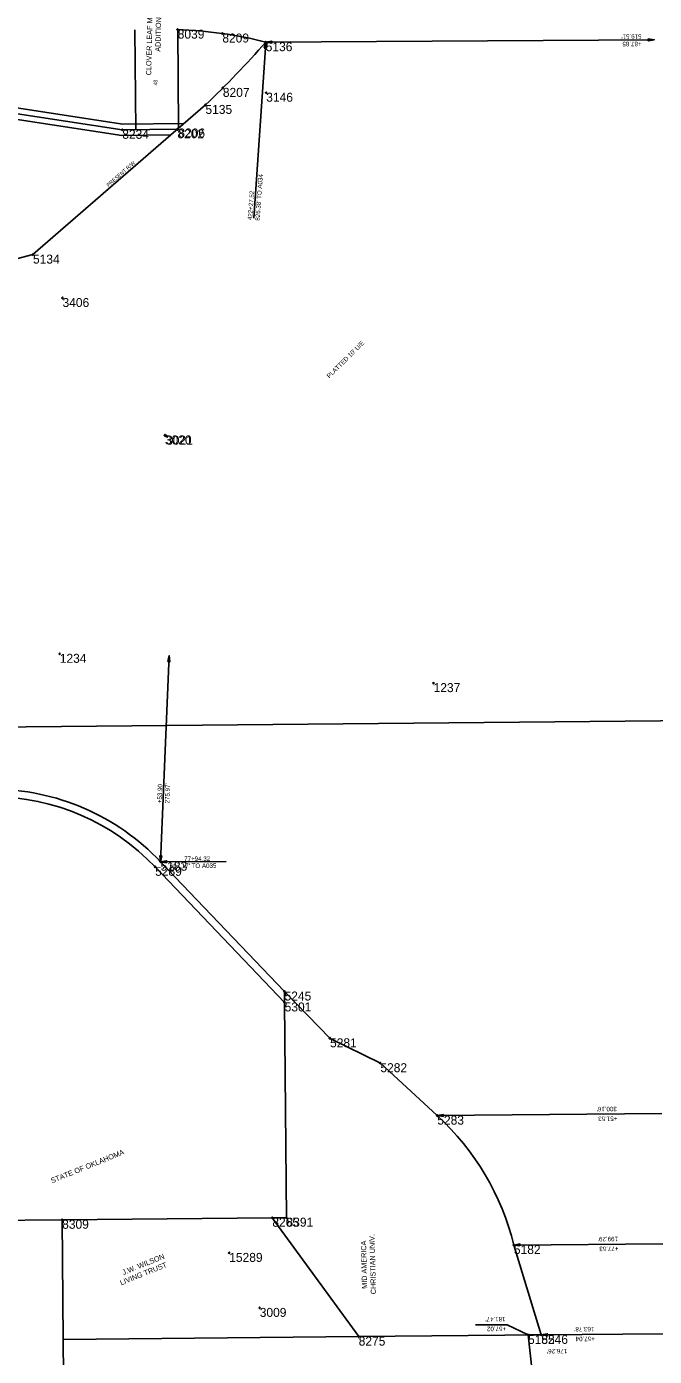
# Model space of a CAD drawing. Extents: x 2145146 to 2158053, y 137507 to 150829.
# Drawn here: x 2149980 to 2150819, y 142146 to 143925 of the extents above; entities that cross this region are included whole.
import ezdxf

# ---------------------------------------------------------------- set-up
doc = ezdxf.new("R2010")
doc.units = 0
for name, color, linetype in [('ALIGN_Cogo Points', 7, 'Continuous'), ('ALIGN_ROW Dimension', 7, 'Continuous'), ('ALIGN_ROW Line', 7, 'Continuous'), ('ALIGN_ROW Text', 7, 'Continuous'), ('PLSS_Easement', 7, 'Continuous'), ('PLSS_Lot Line', 7, 'Continuous'), ('PLSS_Property Line', 7, 'Continuous'), ('PLSS_Section Line', 7, 'Continuous'), ('PLSS_Text', 7, 'Continuous'), ('PLSS_Text_TURNED OFF', 7, 'Continuous')]:
    doc.layers.add(name, color=color, linetype=linetype)

# ---------------------------------------------------------------- blocks, each defined once
blk = doc.blocks.new('Arrowhd')
at = {"layer": 'PLSS_Property Line'}
blk.add_lwpolyline([(0.125, -0.021), (0.125, 0.021), (0, 0)], close=True, dxfattribs=at)

msp = doc.modelspace()

# ---------------------------------------------------------------- linework, layer by layer
at = {"layer": 'ALIGN_Cogo Points'}
for points in [[(2150182, 143920.7), (2150182, 143921.9), (2150182, 143920.7), (2150180.8, 143920.7), (2150182, 143920.7), (2150182, 143919.5), (2150182, 143920.7), (2150183.2, 143920.7)], [(2150241.7, 143915.5), (2150241.7, 143916.7), (2150241.7, 143915.5), (2150240.5, 143915.5), (2150241.7, 143915.5), (2150241.7, 143914.3), (2150241.7, 143915.5), (2150242.9, 143915.5)], [(2150299.7, 143903.9), (2150299.7, 143905.1), (2150299.7, 143903.9), (2150298.5, 143903.9), (2150299.7, 143903.9), (2150299.7, 143902.7), (2150299.7, 143903.9), (2150300.9, 143903.9)], [(2150242.4, 143842.8), (2150242.4, 143844), (2150242.4, 143842.8), (2150241.2, 143842.8), (2150242.4, 143842.8), (2150242.4, 143841.6), (2150242.4, 143842.8), (2150243.6, 143842.8)], [(2150300.4, 143836.3), (2150300.4, 143837.5), (2150300.4, 143836.3), (2150299.2, 143836.3), (2150300.4, 143836.3), (2150300.4, 143835.1), (2150300.4, 143836.3), (2150301.6, 143836.3)], [(2150219.1, 143820), (2150219.1, 143821.2), (2150219.1, 143820), (2150217.9, 143820), (2150219.1, 143820), (2150219.1, 143818.8), (2150219.1, 143820), (2150220.3, 143820)], [(2150107.9, 143786.7), (2150107.9, 143787.9), (2150107.9, 143786.7), (2150106.7, 143786.7), (2150107.9, 143786.7), (2150107.9, 143785.5), (2150107.9, 143786.7), (2150109.1, 143786.7)], [(2150181.6, 143787.4), (2150181.6, 143788.6), (2150181.6, 143787.4), (2150180.4, 143787.4), (2150181.6, 143787.4), (2150181.6, 143786.2), (2150181.6, 143787.4), (2150182.8, 143787.4)], [(2150182.9, 143788.5), (2150182.9, 143789.7), (2150182.9, 143788.5), (2150181.7, 143788.5), (2150182.9, 143788.5), (2150182.9, 143787.3), (2150182.9, 143788.5), (2150184.1, 143788.5)], [(2149988.5, 143619.8), (2149988.5, 143621), (2149988.5, 143619.8), (2149987.3, 143619.8), (2149988.5, 143619.8), (2149988.5, 143618.6), (2149988.5, 143619.8), (2149989.7, 143619.8)], [(2150028, 143561.7), (2150028, 143562.9), (2150028, 143561.7), (2150026.8, 143561.7), (2150028, 143561.7), (2150028, 143560.5), (2150028, 143561.7), (2150029.2, 143561.7)], [(2150164.9, 143378), (2150164.9, 143379.2), (2150164.9, 143378), (2150163.7, 143378), (2150164.9, 143378), (2150164.9, 143376.8), (2150164.9, 143378), (2150166.1, 143378)], [(2150166.5, 143377.5), (2150166.5, 143378.7), (2150166.5, 143377.5), (2150165.3, 143377.5), (2150166.5, 143377.5), (2150166.5, 143376.3), (2150166.5, 143377.5), (2150167.7, 143377.5)], [(2150024.3, 143085.8), (2150024.3, 143087), (2150024.3, 143085.8), (2150023.1, 143085.8), (2150024.3, 143085.8), (2150024.3, 143084.6), (2150024.3, 143085.8), (2150025.5, 143085.8)], [(2150524.2, 143046.6), (2150524.2, 143047.8), (2150524.2, 143046.6), (2150523, 143046.6), (2150524.2, 143046.6), (2150524.2, 143045.4), (2150524.2, 143046.6), (2150525.4, 143046.6)], [(2150151.8, 142800.9), (2150151.8, 142802.1), (2150151.8, 142800.9), (2150150.6, 142800.9), (2150151.8, 142800.9), (2150151.8, 142799.7), (2150151.8, 142800.9), (2150153, 142800.9)], [(2150159.1, 142807.7), (2150159.1, 142808.9), (2150159.1, 142807.7), (2150157.9, 142807.7), (2150159.1, 142807.7), (2150159.1, 142806.5), (2150159.1, 142807.7), (2150160.3, 142807.7)], [(2150324.9, 142634.1), (2150324.9, 142635.3), (2150324.9, 142634.1), (2150323.7, 142634.1), (2150324.9, 142634.1), (2150324.9, 142632.9), (2150324.9, 142634.1), (2150326.1, 142634.1)], [(2150325, 142619.5), (2150325, 142620.7), (2150325, 142619.5), (2150323.8, 142619.5), (2150325, 142619.5), (2150325, 142618.3), (2150325, 142619.5), (2150326.2, 142619.5)], [(2150385.7, 142571.5), (2150385.7, 142572.7), (2150385.7, 142571.5), (2150384.5, 142571.5), (2150385.7, 142571.5), (2150385.7, 142570.3), (2150385.7, 142571.5), (2150386.9, 142571.5)], [(2150453, 142538.2), (2150453, 142539.4), (2150453, 142538.2), (2150451.8, 142538.2), (2150453, 142538.2), (2150453, 142537), (2150453, 142538.2), (2150454.2, 142538.2)], [(2150529.1, 142468.1), (2150529.1, 142469.3), (2150529.1, 142468.1), (2150527.9, 142468.1), (2150529.1, 142468.1), (2150529.1, 142466.9), (2150529.1, 142468.1), (2150530.3, 142468.1)], [(2150027.5, 142328.8), (2150027.5, 142330), (2150027.5, 142328.8), (2150026.3, 142328.8), (2150027.5, 142328.8), (2150027.5, 142327.6), (2150027.5, 142328.8), (2150028.7, 142328.8)], [(2150308.5, 142331.5), (2150308.5, 142332.7), (2150308.5, 142331.5), (2150307.3, 142331.5), (2150308.5, 142331.5), (2150308.5, 142330.3), (2150308.5, 142331.5), (2150309.7, 142331.5)], [(2150327.5, 142331.6), (2150327.5, 142332.8), (2150327.5, 142331.6), (2150326.3, 142331.6), (2150327.5, 142331.6), (2150327.5, 142330.4), (2150327.5, 142331.6), (2150328.7, 142331.6)], [(2150250.9, 142284.5), (2150250.9, 142285.7), (2150250.9, 142284.5), (2150249.7, 142284.5), (2150250.9, 142284.5), (2150250.9, 142283.3), (2150250.9, 142284.5), (2150252.1, 142284.5)], [(2150631.5, 142295), (2150631.5, 142296.2), (2150631.5, 142295), (2150630.3, 142295), (2150631.5, 142295), (2150631.5, 142293.8), (2150631.5, 142295), (2150632.7, 142295)], [(2150291.7, 142210.9), (2150291.7, 142212.1), (2150291.7, 142210.9), (2150290.5, 142210.9), (2150291.7, 142210.9), (2150291.7, 142209.7), (2150291.7, 142210.9), (2150292.9, 142210.9)], [(2150650.4, 142174.7), (2150650.4, 142175.9), (2150650.4, 142174.7), (2150649.2, 142174.7), (2150650.4, 142174.7), (2150650.4, 142173.5), (2150650.4, 142174.7), (2150651.6, 142174.7)], [(2150668.1, 142174.8), (2150668.1, 142176), (2150668.1, 142174.8), (2150666.9, 142174.8), (2150668.1, 142174.8), (2150668.1, 142173.6), (2150668.1, 142174.8), (2150669.3, 142174.8)], [(2150424, 142172.5), (2150424, 142173.7), (2150424, 142172.5), (2150422.8, 142172.5), (2150424, 142172.5), (2150424, 142171.3), (2150424, 142172.5), (2150425.2, 142172.5)]]:
    msp.add_lwpolyline(points, dxfattribs=at)
at = {"layer": 'ALIGN_ROW Dimension'}
for points in [[(2150299.7, 143902.7), (2150283.9, 143668.5)], [(2150299.6, 143904), (2150819.2, 143907.1)], [(2150159.1, 142807.7), (2150170.6, 143083.4)], [(2150159.2, 142807.7), (2150247, 142807.9)], [(2150529.1, 142468.1), (2150829.3, 142470.8)], [(2150631.5, 142295), (2150830.8, 142296.8)], [(2150650.4, 142174.8), (2150622.4, 142188.4), (2150580.3, 142188.4)], [(2150668.1, 142174.8), (2150831.9, 142176.3)]]:
    msp.add_lwpolyline(points, dxfattribs=at)
for points in [[(2150168.9, 143075.4), (2150171.6, 143075.3), (2150170.6, 143083.4)], [(2150160.9, 142815.7), (2150158.2, 142815.8), (2150159.2, 142807.7)]]:
    msp.add_lwpolyline(points, close=True, dxfattribs=at)
at = {"layer": 'ALIGN_ROW Line'}
for points in [[(2149868, 143567.6), (2149863.4, 143587.1), (2149988.5, 143619.8), (2150172.9, 143779.8), (2150219.1, 143820)], [(2150159.1, 142807.7), (2150159.1, 142807.7), (2150324.9, 142634.1), (2150385.7, 142571.5), (2150453, 142538.2), (2150529.1, 142468.1)], [(2150631.5, 142295), (2150631.5, 142295), (2150668.1, 142174.8), (2150650.4, 142174.7), (2150656, 142126), (2150672.7, 142127.9), (2150688.4, 141967.3)]]:
    msp.add_lwpolyline(points, dxfattribs=at)
for centre, radius, start, end in [((2150164.9, 143378), 543, 75.6265, 88.2022), ((2149252.3, 144828.9), 1397.4, 313.7809, 318.5535), ((2149933.8, 142594.6), 310.1, 43.3958, 89.9357), ((2150291.7, 142210.9), 350.1, 13.9103, 47.2955)]:
    msp.add_arc(centre, radius, start, end, dxfattribs=at)
at = {"layer": 'PLSS_Easement'}
for points in [[(2149823.8, 143837.8), (2150108.5, 143794.2), (2150190.3, 143795)], [(2149827.6, 143822), (2150107.4, 143779.2), (2150172.9, 143779.8)], [(2150151.8, 142800.9), (2150151.8, 142800.9), (2150325, 142619.5), (2150324.9, 142634.1)]]:
    msp.add_lwpolyline(points, dxfattribs=at)
msp.add_arc((2149933.8, 142594.6), 300.1, 43.4233, 89.9173, dxfattribs=at)
at = {"layer": 'PLSS_Lot Line'}
for points in [[(2150125.9, 143786.9), (2150124.7, 143920.6)], [(2150182.9, 143788.5), (2150182, 143920.7)], [(2149804.3, 143833.2), (2150107.9, 143786.7), (2150181.6, 143787.4)]]:
    msp.add_lwpolyline(points, dxfattribs=at)
at = {"layer": 'PLSS_Property Line'}
for points in [[(2150424, 142172.5), (2150029, 142168.8), (2150027.5, 142328.8), (2149927.6, 142327.8), (2149922.4, 142907.1)], [(2150308.5, 142331.5), (2150327.5, 142331.6), (2150325, 142619.5)], [(2150308.5, 142331.5), (2150027.5, 142328.8)], [(2150308.5, 142331.5), (2150424, 142172.5), (2150668.1, 142174.8)], [(2150033.3, 141678.8), (2150029, 142168.8)]]:
    msp.add_lwpolyline(points, dxfattribs=at)
at = {"layer": 'PLSS_Section Line'}
msp.add_lwpolyline([(2148283.1, 142972.3), (2150921.7, 142997.3)], dxfattribs=at)

# ---------------------------------------------------------------- block references
at = {"layer": 'ALIGN_ROW Dimension'}
for p, xscale, yscale, rotation in [((2150299.7, 143904), 64.99999999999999, 65.00000000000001, -93.8366707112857), ((2150299.6, 143904), 64.99999999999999, 65, 0.34425883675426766), ((2150819.2, 143907.1), 65.00000000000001, 64.99999999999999, -179.65177652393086), ((2150159.1, 142807.7), 65, 65.00000000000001, 0.5014925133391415), ((2150529.1, 142468.1), 65.00000000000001, 65, 0.7805293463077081), ((2150631.5, 142295), 65.00000000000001, 65, 0.7805293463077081), ((2150668.1, 142174.8), 65.00000000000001, 65, 0.7805293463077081)]:
    msp.add_blockref('Arrowhd', p, dxfattribs=dict(at, xscale=xscale, yscale=yscale, rotation=rotation))

# ---------------------------------------------------------------- texts
at = {"layer": 'ALIGN_Cogo Points'}
for s, p in [('8039', (2150182, 143908.7)), ('8209', (2150241.7, 143903.5)), ('5136', (2150299.7, 143891.9)), ('8207', (2150242.4, 143830.8)), ('3146', (2150300.4, 143824.3)), ('5135', (2150219.1, 143808)), ('8234', (2150107.9, 143774.7)), ('8202', (2150181.6, 143775.4)), ('8206', (2150182.9, 143776.5)), ('5134', (2149988.5, 143607.8)), ('3406', (2150028, 143549.7)), ('3020', (2150164.9, 143366)), ('3021', (2150166.5, 143365.5)), ('1234', (2150024.3, 143073.8)), ('1237', (2150524.2, 143034.6)), ('5289', (2150151.8, 142788.9)), ('5183', (2150159.1, 142795.7)), ('5245', (2150324.9, 142622.1)), ('5301', (2150325, 142607.5)), ('5281', (2150385.7, 142559.5)), ('5282', (2150453, 142526.2)), ('5283', (2150529.1, 142456.1)), ('8309', (2150027.5, 142316.8)), ('8265', (2150308.5, 142319.5)), ('8391', (2150327.5, 142319.6)), ('15289', (2150250.9, 142272.5)), ('5182', (2150631.5, 142283)), ('3009', (2150291.7, 142198.9)), ('5185', (2150650.4, 142162.7)), ('5246', (2150668.1, 142162.8)), ('8275', (2150424, 142160.5))]:
    msp.add_text(s, height=12, dxfattribs=at).set_placement(p)
at = {"layer": 'ALIGN_ROW Dimension'}
for s, rotation, p in [("519.51'", 180, (2150802.2, 143914.6)), ('+87.85', 180, (2150802.2, 143904.5)), ("826.38' TO A034", 85.9114, (2150291.5, 143665)), ('422+27.52', 85.9114, (2150281.4, 143665.7)), ('+53.90', 88.068, (2150160.6, 142886)), ("275.97' ", 88.068, (2150170.8, 142885.6)), ('77+94.32', 0.1737, (2150190.7, 142808.8)), ("667.17' TO A035 ", 0.1737, (2150171.4, 142799.3)), ("300.16'", 180.3718, (2150769.1, 142480)), ('+51.53', 180.3718, (2150769.8, 142467)), ("199.29'", 180.3718, (2150770.7, 142306.1)), ('+77.53', 180.3718, (2150771.3, 142293)), ("181.47'", 180.3718, (2150620.4, 142198.9)), ('+57.02', 180.3718, (2150621.1, 142185.9)), ("163.78'", 180.3718, (2150739.1, 142185.6)), ("176.26'", 180.3718, (2150702.7, 142156.1)), ('+57.04', 180.3718, (2150739.7, 142172.5))]:
    msp.add_text(s, height=6, rotation=rotation, dxfattribs=at).set_placement(p)
at = {"layer": 'ALIGN_ROW Text'}
msp.add_text('PRESENT R/W', height=5, rotation=41.36, dxfattribs=at).set_placement((2150089.6, 143710))
at = {"layer": 'PLSS_Text'}
for s, height, rotation, p in [('48', 5, 90, (2150154.9, 143846)), ("PLATTED 10' U/E", 6, 44.7803, (2150384.8, 143454))]:
    msp.add_text(s, height=height, rotation=rotation, dxfattribs=at).set_placement(p)
at = {"layer": 'PLSS_Text_TURNED OFF'}
for s, rotation, p in [('CLOVER LEAF MANOR', 88.6723, (2150146.5, 143859.6)), ('ADDITION', 88.6723, (2150158.9, 143891.1)), ('STATE OF OKLAHOMA', 22, (2150014, 142377.5)), ('MID AMERICA', 91.4293, (2150435.4, 142236.6)), ('CHRISTIAN UNIV.', 91.4293, (2150447.2, 142229.3)), ('J.W. WILSON', 22, (2150109.4, 142254.7)), ('LIVING TRUST', 22, (2150106.5, 142241))]:
    msp.add_text(s, height=7, rotation=rotation, dxfattribs=at).set_placement(p)

doc.saveas('drawing.dxf')
